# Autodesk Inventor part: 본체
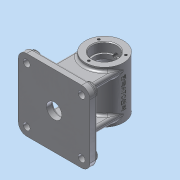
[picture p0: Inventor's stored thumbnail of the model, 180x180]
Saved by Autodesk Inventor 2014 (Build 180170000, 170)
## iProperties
Created: 2025-10
Part Number: 본체
Material: 알루미늄 6061
Document SubType Name: Modeling
Designer: dg
Density: 2.71 g/cm^3
Appearance: 알루미늄 - 평지
Mass: 505.687 g
Surface Area: 499.386 cm^2
Volume: 186.6 cm^3
Author: dg
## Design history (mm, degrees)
sketch "스케치1"
  geometry: C1 r 25 at (0, 0); 1 further point
  constraints: 1 centre point, 1 coincident
  dimensions: "d0" = 50 diameter of C1
extrude "돌출1" new body sketch "스케치1" distance "d1" = 68; taper "d2" = 0 deg
sketch "스케치2"
  geometry: L1 (0, 0)-(16, 0); L2 (16, 0)-(16, 11.7); L3 (15.7, 12)-(13.5, 12); L4 (13.5, 12)-(13.5, 17.742); L5 (13.5, 17.742)-(19.598, 28.304); L6 (20, 29.804)-(20, 38.196); L7 (19.598, 39.696)-(13.5, 50.258); L8 (13.5, 50.258)-(13.5, 56); L9 (13.5, 56)-(15.7, 56); L10 (25, 68)-(-25, 68) reference; L11 (16, 56.3)-(16, 68); L12 (25, 0)-(25, 68) reference; L13 (25, 34)-(-16.235, 34) reference; L14 (16, 68)-(0, 68); L15 (0, 68)-(0, 0); A1 r 3 centre (17, 38.196) between (20, 38.196) and (19.598, 39.696); A2 r 3 centre (17, 29.804) between (19.598, 28.304) and (20, 29.804); A3 r 0.3 centre (15.7, 56.3) between (15.7, 56) and (16, 56.3); A4 r 0.3 centre (15.7, 11.7) between (16, 11.7) and (15.7, 12); 4 further points
  constraints: 26 end point, 9 point on line, 8 point on circle, 8 tangent, 4 centre point, 4 perpendicular, 3 parallel, 2 midpoint, 1 equal radius, 1 horizontal, 1 other
  dimensions: "d3" = 16 distance of L1.start L1.end; "d4" = 12 distance of L1.end point (16, 12); "d6" = 10 distance of point (20, 29) point (20, 39); "d7" = 12 distance of point (16, 56) L11.end; "d13" = 3 radius of A1; "d14" = 3 radius of A2; "d15" = 0.3 radius of A3; "d16" = 13.5 distance between parallel lines of L15 L4; "d17" = 20 distance between parallel lines of L15 L6; "d18" = 16 distance between parallel lines of L15 L11; "d19" = 13.5 distance between parallel lines of L15 L8; "d20" = 30 deg angle of L15 L7
revolve "회전1" sketch "스케치2" stored, may be unused: angle "d21" = 90 deg
node "작업 평면1"
sketch "스케치3"
  geometry: L1 (-47, 81)-(47, 81); L2 (47, 81)-(47, -13); L3 (47, -13)-(-47, -13); L4 (-47, -13)-(-47, 81); L5 (-47, 81)-(47, -13); L6 (47, 81)-(-47, -13); L7 (-25, 0)-(25, 0) reference; L8 (0, 91.691)-(0, -41.734) reference; 2 further points
  constraints: 14 end point, 2 midpoint, 2 parallel, 2 perpendicular, 1 horizontal, 1 vertical
  dimensions: "d23" = 94 distance of L2.end L3.end; "d24" = 94 distance of L1.end L2.end; "d25" = 13 distance between parallel lines of L3 L7; "d26" = 47 distance between parallel lines of L2 L8
extrude "돌출2" join sketch "스케치3" distance "d27" = 10; taper "d28" = 0 deg
sketch "스케치4"
  geometry: L1 (-47, -81)-(47, -81) reference; L2 (47, -81)-(47, 13) reference; L3 (47, 13)-(-47, 13) reference; L4 (-47, 13)-(-47, -81) reference; 1 further point
fillet "모깎기1" dims "d29" = 11
sketch "스케치5"
  geometry: L1 (36, 13)-(-36, 13) reference; L2 (-47, 2)-(-47, -70) reference; C1 r 8 at (-36, 2); C2 r 8 at (36, 2); C3 r 8 at (-36, -70); C4 r 8 at (36, -70); A1 r 11 centre (-36, 2) between (-36, 13) and (-47, 2) reference; 1 further point
  constraints: 4 centre point, 1 coincident, 1 horizontal, 1 vertical, 6 other
  dimensions: "d30" = 16 diameter of C1; "d33" = 72 distance of C1.centre C2.centre; "d36" = 72 distance of C1.centre C3.centre
extrude "돌출3" join sketch "스케치5" distance "d39" = 3; taper "d40" = 0 deg
sketch "스케치6"
  geometry: L1 (72, 83)-(0, 83) reference; L2 (-11, 72)-(-11, 0) reference; C1 r 8 at (0, 72) reference; C2 r 4.5 at (0, 72); C3 r 4.5 at (72, 72); C4 r 4.5 at (0, 0); C5 r 4.5 at (72, 0); 1 further point
  constraints: 4 centre point, 1 coincident, 1 horizontal, 1 vertical, 6 other
  dimensions: "d41" = 9 diameter of C2; "d44" = 72 distance of C2.centre C3.centre; "d47" = 72 distance of C2.centre C4.centre
extrude "돌출4" cut sketch "스케치6" distance "d50" = 20; taper "d51" = 0 deg
sketch "스케치7"
  geometry: L1 (-47, 2)-(-47, -70) reference; L2 (47, -70)-(47, 2) reference; L3 (-25, -5)-(25, -5); L4 (25, -5)-(25, -13); L5 (25, -13)-(-25, -13); L6 (-25, -13)-(-25, -5); L7 (-25, -5)-(25, -13); L8 (25, -5)-(-25, -13); L9 (-47, -34)-(47, -34) reference; L10 (-25, -63)-(25, -63); L11 (25, -55)-(-25, -55); L12 (-25, -55)-(-25, -63); L13 (25, -63)-(25, -55); 2 further points
  constraints: 22 end point, 4 midpoint, 4 symmetric about line, 2 horizontal, 2 parallel, 1 perpendicular
  dimensions: "d52" = 50 distance of L4.end L5.end; "d53" = 8 distance of L3.end L4.end; "d55" = 22 distance between parallel lines of L1 L6; "d128" = 42 distance between parallel lines of L11 L5
sketch "스케치8"
  geometry: L1 (-36, -81)-(36, -81) reference; L2 (47, -70)-(47, 2) reference; C1 r 10 at (0, -34); 1 further point
  constraints: 1 centre point
  dimensions: "d58" = 20 diameter of C1; "d59" = 47 distance from line of L1 C1.centre; "d60" = 47 distance from line of L2 C1.centre
extrude "돌출6" cut sketch "스케치8" distance "d61" = 56; taper "d62" = 0 deg
sketch "스케치9"
  geometry: 1 further point
node "작업 평면2"
sketch "스케치10"
  geometry: L1 (25, 68)-(-25, 68) reference; L2 (-25, 0)-(-25, 68) reference; C1 r 6 at (0, 34); 1 further point
  constraints: 1 centre point
  dimensions: "d64" = 12 diameter of C1
extrude "돌출7" join sketch "스케치10" distance "d65" = 5; taper "d66" = 0 deg
sketch "스케치11"
  geometry: C1 r 6 at (0, 0) reference; 2 further points
  constraints: 1 coincident
hole "구멍1" sketch "스케치11" at (0, 0) diameter "d67" = 5.188; stored, may be unused: countersink angle "d71" = 90 deg, drill point angle "d73" = 118 deg; dims "d68" = 6, "d69" = 4, "d70" = 2, "d72" = 8
node "작업 평면3"
sketch "스케치12"
  geometry: L1 (25, 68)-(-25, 68) reference; L2 (-25, 0)-(-25, 68) reference; L3 (-25, 0)-(25, 0) reference; C1 r 5 at (0, 56); C2 r 5 at (0, 12); 1 further point
  constraints: 2 centre point
  dimensions: "d75" = 10 diameter of C1; "d76" = 12 distance from line of L1 C1.centre; "d77" = 10 diameter of C2; "d78" = 12 distance from line of L3 C2.centre
extrude "돌출8" join sketch "스케치12" distance "d79" = 5; taper "d80" = 0 deg
sketch "스케치13"
  geometry: C1 r 5 at (0, 0) reference; C2 r 5 at (0, -44) reference; 3 further points
  constraints: 2 coincident
hole "구멍2" sketch "스케치13" at (0, -44), (0, 0) diameter "d81" = 5.188; stored, may be unused: countersink angle "d85" = 90 deg, drill point angle "d87" = 118 deg; dims "d82" = 6, "d83" = 6.6, "d84" = 2, "d86" = 20
sketch "스케치14"
  geometry: L1 (0, 0)-(34.596, 19.974); L2 (0, 0)-(-39.027, 22.532); L3 (0, 35.65)-(0, -22.82) reference; C1 r 25 at (0, 0) reference; A1 r 20.5 centre (0, 0) between (0, -20.5) and (17.754, 10.25); 1 further point
  constraints: 6 end point, 3 point on circle, 3 point on line, 2 vertical, 1 centre point, 1 coincident
  dimensions: "d88" = 60 deg angle of L3 L2; "d89" = 60 deg angle of L1 L3; "d90" = 41 diameter of A1
node "작업 평면4"
fillet "모깎기4" dims "d104" = 3
fillet "모깎기5" dims "d105" = 3
fillet "모깎기6" dims "d106" = 3
node "작업 평면7"
sketch "스케치18"
  geometry: L1 (70, 41)-(70, 91) reference; L2 (72, 0)-(0, 0) reference; 2 further points
  constraints: 1 other
  dimensions: "d118" = 34 distance from line of L1 point (36, 66); "d119" = 66 distance from line of L2 point (36, 66)
feature "엠보싱2" sketch "스케치18" dims "d0" = 50, "d120" = 0.5, "d121" = 0
chamfer "모따기1" distance "d122" = 1; stored, may be unused: second distance "d123" = 2, angle "d124" = 45 deg
chamfer "모따기2" distance "d125" = 1; stored, may be unused: second distance "d126" = 2, angle "d127" = 45 deg
extrude "돌출9" join sketch "스케치7" distance "d129" = 56; taper "d130" = 0 deg
feature "면 삭제3"
fillet "모깎기10" dims "d131" = 3
fillet "모깎기11" dims "d132" = 3
hole "구멍4" sketch "스케치14" diameter "d133" = 3.242; stored, may be unused: countersink angle "d137" = 90 deg, drill point angle "d139" = 118 deg; dims "d134" = 8, "d135" = 6.6, "d136" = 2, "d138" = 10
node "솔리드1"
mirror "대칭2"
node "작업 평면8"
other parameters: "d22" = -66, "d63" = -28, "d74" = 28, "d98" = -34, "d117" = 0
